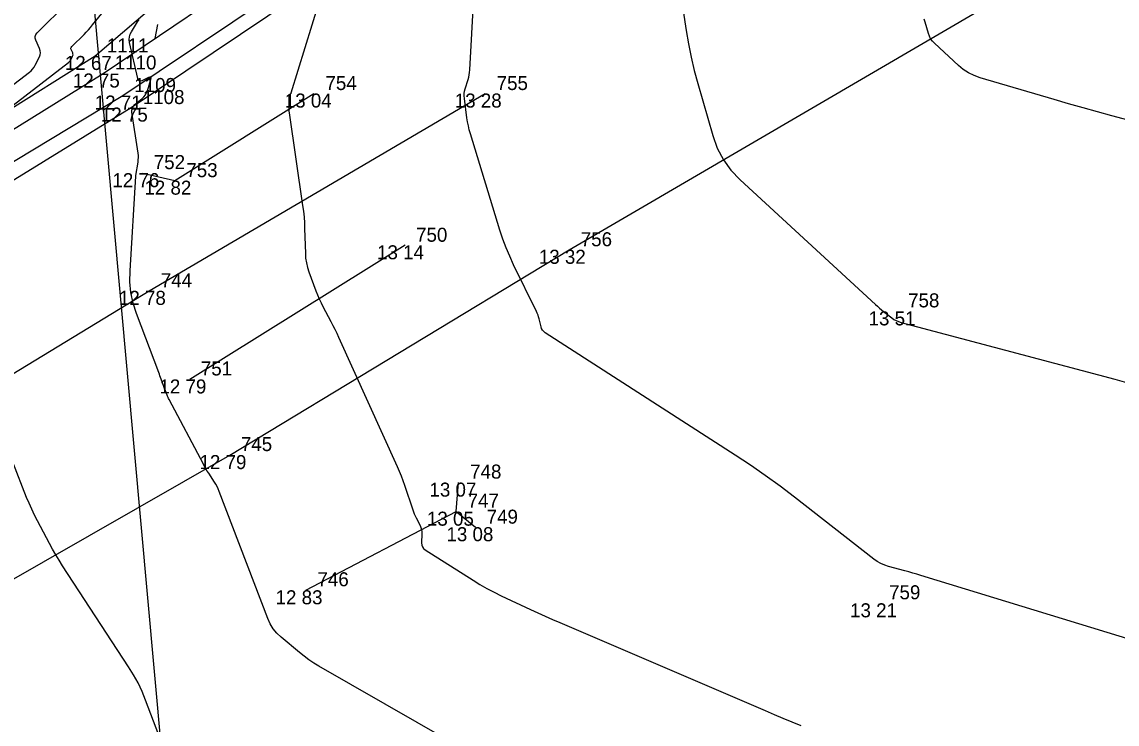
# Model space of a CAD drawing. Extents: x -711234 to -710007, y -1026313 to -1025448.
# Drawn here: x -710937.91 to -710916.03, y -1025865.86 to -1025851.84 of the extents above; entities that cross this region are included whole.
import ezdxf

# ---------------------------------------------------------------- set-up
doc = ezdxf.new("R2010")
doc.units = 0
for name, color, linetype in [('Ex_Major Contours', 7, 'Continuous'), ('Ex_Minor Contours', 7, 'Continuous'), ('Z_body', 7, 'Continuous'), ('Z_body_cisla', 7, 'Continuous'), ('Z_body_vysky_redukovane', 7, 'Continuous'), ('Z_hrany_paty', 7, 'Continuous'), ('Z_katastr_hranice', 7, 'Continuous'), ('Z_komunikace', 7, 'Continuous'), ('Z_svodidla', 7, 'Continuous'), ('Z_svodidla_znacky', 7, 'Continuous'), ('Z_vdz12_plna', 7, 'Continuous'), ('Z_vdz12_prerusovana', 7, 'Continuous'), ('Z_vdz25_plna', 7, 'Continuous'), ('Z_vdz_sipky', 7, 'Continuous')]:
    doc.layers.add(name, color=color, linetype=linetype)

# ---------------------------------------------------------------- blocks, each defined once
blk = doc.blocks.new('POINT_DISPLAY')
blk.add_line((0, 0), (0, 0))
blk = doc.blocks.new('Z529')
blk.add_line((0, 0), (0.2, 0.2))

msp = doc.modelspace()

# ---------------------------------------------------------------- linework, layer by layer
at = {"layer": 'Ex_Major Contours'}
msp.add_lwpolyline([(-710931.842, -1025850.992), (-710932.539, -1025853.262), (-710932.541, -1025853.268), (-710932.545, -1025853.274), (-710932.548, -1025853.279), (-710932.553, -1025853.283), (-710932.573, -1025853.3), (-710932.578, -1025853.305), (-710932.581, -1025853.31), (-710932.583, -1025853.315), (-710932.584, -1025853.322), (-710932.585, -1025853.517), (-710932.585, -1025853.552), (-710932.583, -1025853.586), (-710932.58, -1025853.621), (-710932.575, -1025853.655), (-710932.306, -1025855.508), (-710932.291, -1025855.622), (-710932.279, -1025855.736), (-710932.271, -1025855.851), (-710932.266, -1025855.965), (-710932.252, -1025856.462), (-710932.246, -1025856.557), (-710932.232, -1025856.651), (-710932.21, -1025856.743), (-710932.18, -1025856.833), (-710932.04, -1025857.212), (-710932.009, -1025857.291), (-710931.975, -1025857.37), (-710931.939, -1025857.447), (-710931.9, -1025857.523), (-710931.74, -1025857.825), (-710931.701, -1025857.901), (-710931.662, -1025857.977), (-710931.625, -1025858.054), (-710931.589, -1025858.132), (-710930.416, -1025860.719), (-710930.375, -1025860.811), (-710930.337, -1025860.904), (-710930.302, -1025860.999), (-710930.269, -1025861.094), (-710930.107, -1025861.585), (-710930.092, -1025861.626), (-710930.077, -1025861.666), (-710930.059, -1025861.705), (-710930.04, -1025861.745), (-710929.961, -1025861.899), (-710929.944, -1025861.939), (-710929.932, -1025861.979), (-710929.926, -1025862.021), (-710929.925, -1025862.064), (-710929.932, -1025862.244), (-710929.928, -1025862.286), (-710929.915, -1025862.323), (-710929.892, -1025862.355), (-710929.86, -1025862.381), (-710928.901, -1025862.991), (-710928.764, -1025863.075), (-710928.624, -1025863.155), (-710928.482, -1025863.23), (-710928.338, -1025863.3), (-710927.754, -1025863.572), (-710927.608, -1025863.64), (-710927.461, -1025863.706), (-710927.314, -1025863.771), (-710927.166, -1025863.835), (-710923.065, -1025865.592), (-710922.888, -1025865.668), (-710922.71, -1025865.743), (-710922.532, -1025865.817), (-710922.354, -1025865.89)], dxfattribs=at)
at = {"layer": 'Ex_Minor Contours'}
for points in [[(-710925.394, -1025847.076), (-710924.643, -1025852.014), (-710924.598, -1025852.28), (-710924.544, -1025852.545), (-710924.482, -1025852.808), (-710924.412, -1025853.069), (-710924.113, -1025854.109), (-710924.022, -1025854.36), (-710923.901, -1025854.591), (-710923.749, -1025854.803), (-710923.565, -1025854.996), (-710920.862, -1025857.484), (-710920.823, -1025857.519), (-710920.783, -1025857.554), (-710920.742, -1025857.587), (-710920.701, -1025857.62), (-710920.535, -1025857.75), (-710920.493, -1025857.78), (-710920.448, -1025857.805), (-710920.4, -1025857.825), (-710920.351, -1025857.841), (-710916.405, -1025858.886), (-710916.081, -1025858.974), (-710915.757, -1025859.065)], [(-710913.403, -1025864.897), (-710919.953, -1025862.893), (-710920.033, -1025862.869), (-710920.113, -1025862.846), (-710920.194, -1025862.823), (-710920.275, -1025862.801), (-710920.599, -1025862.716), (-710920.678, -1025862.69), (-710920.753, -1025862.658), (-710920.825, -1025862.617), (-710920.893, -1025862.57), (-710922.48, -1025861.33), (-710922.769, -1025861.11), (-710923.063, -1025860.896), (-710923.362, -1025860.689), (-710923.665, -1025860.489), (-710927.458, -1025858.049), (-710927.488, -1025858.025), (-710927.513, -1025857.997), (-710927.532, -1025857.964), (-710927.544, -1025857.927), (-710927.58, -1025857.77), (-710927.591, -1025857.732), (-710927.603, -1025857.694), (-710927.618, -1025857.656), (-710927.634, -1025857.62), (-710928.091, -1025856.689), (-710928.17, -1025856.521), (-710928.242, -1025856.35), (-710928.307, -1025856.176), (-710928.365, -1025855.999), (-710928.955, -1025854.076), (-710928.977, -1025853.997), (-710928.996, -1025853.918), (-710929.012, -1025853.838), (-710929.024, -1025853.757), (-710929.075, -1025853.367), (-710929.079, -1025853.319), (-710929.077, -1025853.271), (-710929.071, -1025853.224), (-710929.059, -1025853.177), (-710929.002, -1025852.99), (-710928.989, -1025852.943), (-710928.979, -1025852.896), (-710928.972, -1025852.848), (-710928.968, -1025852.8), (-710928.731, -1025848.558)], [(-710938.418, -1025853.749), (-710936.983, -1025852.652), (-710936.969, -1025852.64), (-710936.956, -1025852.626), (-710936.945, -1025852.611), (-710936.936, -1025852.595), (-710936.902, -1025852.526), (-710936.895, -1025852.51), (-710936.893, -1025852.494), (-710936.895, -1025852.477), (-710936.9, -1025852.46), (-710936.93, -1025852.393), (-710936.935, -1025852.377), (-710936.935, -1025852.362), (-710936.93, -1025852.348), (-710936.92, -1025852.334), (-710936.674, -1025852.089), (-710936.63, -1025852.044), (-710936.586, -1025851.997), (-710936.544, -1025851.949), (-710936.503, -1025851.901), (-710934.103, -1025848.984)], [(-710941.313, -1025855.556), (-710937.766, -1025852.846), (-710937.731, -1025852.816), (-710937.7, -1025852.782), (-710937.673, -1025852.746), (-710937.65, -1025852.706), (-710937.566, -1025852.536), (-710937.55, -1025852.495), (-710937.544, -1025852.455), (-710937.549, -1025852.414), (-710937.562, -1025852.372), (-710937.637, -1025852.207), (-710937.649, -1025852.167), (-710937.649, -1025852.129), (-710937.636, -1025852.094), (-710937.61, -1025852.061), (-710937.004, -1025851.456)], [(-710928.051, -1025866.957), (-710931.98, -1025864.705), (-710932.082, -1025864.644), (-710932.181, -1025864.578), (-710932.277, -1025864.508), (-710932.37, -1025864.434), (-710932.736, -1025864.129), (-710932.822, -1025864.048), (-710932.895, -1025863.958), (-710932.956, -1025863.86), (-710933.004, -1025863.753), (-710933.973, -1025861.214), (-710933.993, -1025861.166), (-710934.016, -1025861.119), (-710934.041, -1025861.073), (-710934.068, -1025861.029), (-710934.183, -1025860.853), (-710934.211, -1025860.809), (-710934.238, -1025860.764), (-710934.265, -1025860.718), (-710934.29, -1025860.672), (-710934.975, -1025859.379), (-710934.986, -1025859.358), (-710934.995, -1025859.337), (-710935.005, -1025859.316), (-710935.014, -1025859.294), (-710935.047, -1025859.208), (-710935.056, -1025859.186), (-710935.064, -1025859.164), (-710935.072, -1025859.142), (-710935.08, -1025859.121), (-710935.134, -1025858.972), (-710935.146, -1025858.94), (-710935.157, -1025858.908), (-710935.169, -1025858.876), (-710935.181, -1025858.844), (-710935.626, -1025857.666), (-710935.692, -1025857.457), (-710935.736, -1025857.245), (-710935.757, -1025857.029), (-710935.755, -1025856.81), (-710935.64, -1025854.921), (-710935.639, -1025854.916), (-710935.636, -1025854.91), (-710935.636, -1025854.907), (-710935.594, -1025854.64), (-710935.589, -1025854.595), (-710935.587, -1025854.55), (-710935.588, -1025854.505), (-710935.594, -1025854.46), (-710935.716, -1025853.644), (-710935.717, -1025853.599), (-710935.708, -1025853.558), (-710935.688, -1025853.521), (-710935.657, -1025853.489), (-710935.51, -1025853.366), (-710935.476, -1025853.334), (-710935.448, -1025853.298), (-710935.426, -1025853.258), (-710935.409, -1025853.214), (-710935.34, -1025852.99), (-710935.335, -1025852.962), (-710935.341, -1025852.945), (-710935.358, -1025852.942), (-710935.385, -1025852.951), (-710935.519, -1025853.014), (-710935.549, -1025853.023), (-710935.573, -1025853.019), (-710935.59, -1025853.002), (-710935.601, -1025852.973), (-710935.763, -1025852.248), (-710935.77, -1025852.192), (-710935.767, -1025852.139), (-710935.752, -1025852.087), (-710935.727, -1025852.037), (-710935.606, -1025851.84), (-710935.575, -1025851.792)], [(-710914.304, -1025854.199), (-710916.138, -1025853.713), (-710916.428, -1025853.635), (-710916.716, -1025853.556), (-710917.004, -1025853.474), (-710917.292, -1025853.39), (-710918.769, -1025852.955), (-710918.888, -1025852.912), (-710919.001, -1025852.857), (-710919.107, -1025852.788), (-710919.205, -1025852.708), (-710919.686, -1025852.265), (-710919.726, -1025852.223), (-710919.76, -1025852.176), (-710919.786, -1025852.126), (-710919.806, -1025852.071), (-710919.871, -1025851.843), (-710919.887, -1025851.786)], [(-710935.176, -1025866.082), (-710935.443, -1025865.382), (-710935.514, -1025865.209), (-710935.595, -1025865.041), (-710935.684, -1025864.877), (-710935.782, -1025864.718), (-710937.103, -1025862.7), (-710937.172, -1025862.591), (-710937.239, -1025862.481), (-710937.303, -1025862.37), (-710937.365, -1025862.257), (-710937.606, -1025861.802), (-710937.664, -1025861.687), (-710937.719, -1025861.571), (-710937.771, -1025861.453), (-710937.82, -1025861.334), (-710938.094, -1025860.631)]]:
    msp.add_lwpolyline(points, dxfattribs=at)
at = {"layer": 'Z_hrany_paty'}
for p, q in [((-710936.45, -1025852.52), (-710932.38, -1025849.02)), ((-710943.83, -1025857.14), (-710936.45, -1025852.52))]:
    msp.add_line(p, q, dxfattribs=at)
at = {"layer": 'Z_katastr_hranice'}
msp.add_line((-710934.23, -1025876.27), (-710937.26, -1025842.82), dxfattribs=at)
at = {"layer": 'Z_komunikace'}
for p, q in [((-710935.9, -1025853.31), (-710931.25, -1025850.19)), ((-710943.11, -1025857.65), (-710935.9, -1025853.31))]:
    msp.add_line(p, q, dxfattribs=at)
at = {"layer": 'Z_svodidla'}
for p, q in [((-710936.29, -1025852.87), (-710931.65, -1025849.73)), ((-710943.5, -1025857.33), (-710936.29, -1025852.87))]:
    msp.add_line(p, q, dxfattribs=at)
at = {"layer": 'Z_vdz12_plna'}
for p, q in [((-710926.98, -1025856.39), (-710918.6, -1025851.5)), ((-710933.76, -1025860.49), (-710926.98, -1025856.39)), ((-710943.89, -1025862.39), (-710935.37, -1025857.21)), ((-710942.53, -1025865.51), (-710933.76, -1025860.49))]:
    msp.add_line(p, q, dxfattribs=at)
at = {"layer": 'Z_vdz12_prerusovana'}
msp.add_line((-710935.37, -1025857.21), (-710928.66, -1025853.27), dxfattribs=at)
at = {"layer": 'Z_vdz25_plna'}
for p, q in [((-710935.73, -1025853.55), (-710931.06, -1025850.41)), ((-710942.92, -1025857.97), (-710935.73, -1025853.55))]:
    msp.add_line(p, q, dxfattribs=at)
at = {"layer": 'Z_vdz_sipky'}
for p, q in [((-710934.86, -1025855.01), (-710932.08, -1025853.27)), ((-710935.5, -1025854.86), (-710934.86, -1025855.01)), ((-710930.26, -1025856.3), (-710934.56, -1025858.98)), ((-710929.24, -1025861.62), (-710929.19, -1025861.04)), ((-710932.24, -1025863.19), (-710929.24, -1025861.62)), ((-710929.24, -1025861.62), (-710928.85, -1025861.93))]:
    msp.add_line(p, q, dxfattribs=at)

# ---------------------------------------------------------------- block references
at = {"layer": 'Z_body'}
for p in [(-710936.45, -1025852.52), (-710936.29, -1025852.87), (-710935.9, -1025853.31), (-710932.08, -1025853.27), (-710928.66, -1025853.27), (-710935.73, -1025853.55), (-710935.5, -1025854.86), (-710934.86, -1025855.01), (-710930.26, -1025856.3), (-710926.98, -1025856.39), (-710935.37, -1025857.21), (-710920.44, -1025857.62), (-710934.56, -1025858.98), (-710933.76, -1025860.49), (-710929.19, -1025861.04), (-710929.24, -1025861.62), (-710928.85, -1025861.93), (-710932.24, -1025863.19), (-710920.81, -1025863.45)]:
    msp.add_blockref('POINT_DISPLAY', p, dxfattribs=at)
at = {"layer": 'Z_svodidla_znacky', "rotation": 34.1}
msp.add_blockref('Z529', (-710935.25, -1025852.17), dxfattribs=at)

# ---------------------------------------------------------------- texts
at = {"layer": 'Z_body_cisla'}
for s, p in [('1111', (-710936.22, -1025852.45)), ('1110', (-710936.06, -1025852.79)), ('1109', (-710935.67, -1025853.24)), ('754', (-710931.85, -1025853.2)), ('755', (-710928.43, -1025853.2)), ('1108', (-710935.5, -1025853.48)), ('752', (-710935.28, -1025854.78)), ('753', (-710934.63, -1025854.94)), ('750', (-710930.04, -1025856.23)), ('756', (-710926.75, -1025856.32)), ('744', (-710935.14, -1025857.14)), ('758', (-710920.21, -1025857.54)), ('751', (-710934.34, -1025858.9)), ('745', (-710933.54, -1025860.41)), ('748', (-710928.96, -1025860.96)), ('747', (-710929.01, -1025861.54)), ('749', (-710928.63, -1025861.86)), ('746', (-710932.01, -1025863.11)), ('759', (-710920.59, -1025863.37))]:
    msp.add_text(s, height=0.28, dxfattribs=at).set_placement(p)
at = {"layer": 'Z_body_vysky_redukovane'}
for s, p in [('12 67', (-710937.057, -1025852.8)), ('12 75', (-710936.897, -1025853.15)), ('12 71', (-710936.46, -1025853.59)), ('13 04', (-710932.663, -1025853.55)), ('13 28', (-710929.267, -1025853.55)), ('12 75', (-710936.337, -1025853.83)), ('12 76', (-710936.107, -1025855.14)), ('12 82', (-710935.467, -1025855.29)), ('13 14', (-710930.82, -1025856.58)), ('13 32', (-710927.587, -1025856.67)), ('12 78', (-710935.977, -1025857.49)), ('13 51', (-710921, -1025857.9)), ('12 79', (-710935.167, -1025859.26)), ('12 79', (-710934.367, -1025860.77)), ('13 07', (-710929.773, -1025861.32)), ('13 05', (-710929.823, -1025861.9)), ('13 08', (-710929.433, -1025862.21)), ('12 83', (-710932.847, -1025863.47)), ('13 21', (-710921.37, -1025863.73))]:
    msp.add_text(s, height=0.28, dxfattribs=at).set_placement(p)

doc.saveas('drawing.dxf')
